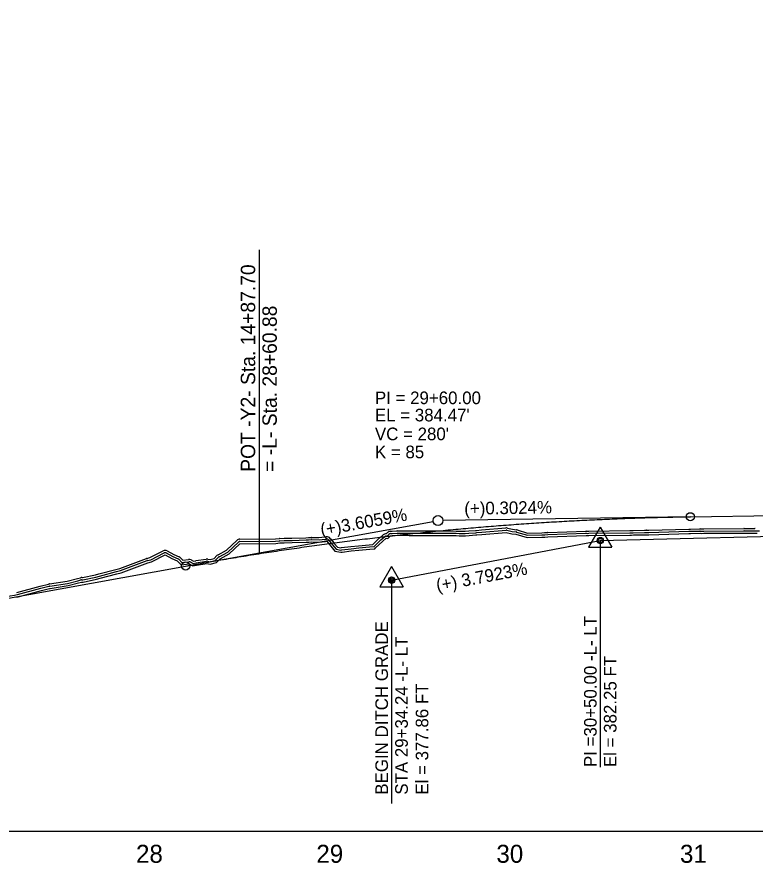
# Model space of a CAD drawing. Extents: x 1625686 to 1640492, y 1161393 to 1175642.
# Drawn here: x 1631930.7 to 1632340.2, y 1174893.1 to 1175362.5 of the extents above; entities that cross this region are included whole.
import ezdxf

# ---------------------------------------------------------------- set-up
doc = ezdxf.new("R2010")
doc.units = 0
for name, color, linetype in [('Exist Profile Cell', 7, 'Continuous'), ('Exist Vertical Profile Ground Line', 7, 'Continuous'), ('Exist Vertical Profile Horizontal Axis Label Major', 7, 'Continuous'), ('Prop PFL Text', 7, 'Continuous'), ('Prop Vertical Profile Curve Label', 7, 'Continuous'), ('Prop Vertical Profile Ditch Grade Left', 7, 'Continuous'), ('Prop Vertical Profile Ditch Grade Left Label', 7, 'Continuous'), ('Prop Vertical Profile Grade', 7, 'Continuous'), ('Prop Vertical Profile Grade Label', 7, 'Continuous'), ('Prop VPI Ditch Grade Left Label', 7, 'Continuous'), ('Prop VPI Label', 7, 'Continuous'), ('Scratch_Level_1', 7, 'Continuous'), ('Scratch_Level_3', 7, 'Continuous'), ('Scratch_Level_5', 7, 'Continuous')]:
    doc.layers.add(name, color=color, linetype=linetype)

msp = doc.modelspace()

# ---------------------------------------------------------------- linework, layer by layer
at = {"layer": 'Exist Profile Cell'}
msp.add_line((1630204.31, 1174910.79), (1634670.63, 1174910.79), dxfattribs=at)
at = {"layer": 'Exist Vertical Profile Ground Line'}
msp.add_lwpolyline([(1631930.43, 1175040.63), (1631931.35, 1175040.89), (1631944.27, 1175044.34), (1631948.74, 1175045.44), (1631949.08, 1175045.51), (1631959.09, 1175047.07), (1631964.89, 1175048.52), (1631966.54, 1175048.97), (1631966.94, 1175048.95), (1631967.49, 1175048.99), (1631974.82, 1175050.58), (1631976.86, 1175051.11), (1631986.19, 1175053.62), (1631988.61, 1175054.19), (1632003.39, 1175059.72), (1632005.36, 1175060.23), (1632012.88, 1175064.05), (1632016.68, 1175062.06), (1632019.64, 1175060.73), (1632021.81, 1175058.61), (1632026.2, 1175059.03), (1632028.28, 1175058), (1632030.37, 1175058.42), (1632036.09, 1175059.3), (1632037.88, 1175058.92), (1632041.38, 1175059.8), (1632043.45, 1175061.95), (1632048.5, 1175064.66), (1632054.43, 1175070.26), (1632074.26, 1175070.42), (1632076.53, 1175070.68), (1632078.98, 1175070.77), (1632083.33, 1175070.9), (1632091.13, 1175071.13), (1632092.6, 1175071.22), (1632094.03, 1175071.31), (1632098.34, 1175071.15), (1632101.87, 1175071.54), (1632102.62, 1175071.63), (1632104.82, 1175068.92), (1632107.09, 1175066.11), (1632110.32, 1175065.52), (1632111.14, 1175065.61), (1632116.2, 1175066.27), (1632120.41, 1175066.66), (1632126.39, 1175067.21), (1632129.18, 1175067.43), (1632129.68, 1175067.92), (1632133.45, 1175071.52), (1632135.56, 1175073.3), (1632136.46, 1175073.17), (1632137.99, 1175074.71), (1632138.95, 1175074.78), (1632141.71, 1175074.97), (1632148.22, 1175074.93), (1632157.49, 1175074.89), (1632163.42, 1175074.86), (1632165.48, 1175074.89), (1632166.76, 1175074.88), (1632174.29, 1175074.81), (1632176.03, 1175074.72), (1632179.5, 1175074.72), (1632181.5, 1175074.86), (1632185.3, 1175075.15), (1632185.89, 1175075.2), (1632188.7, 1175075.48), (1632202.18, 1175076.53), (1632205.23, 1175075.78), (1632207.53, 1175075.56), (1632213.68, 1175073.7), (1632221.97, 1175073.89), (1632223.56, 1175073.94), (1632225.25, 1175074.09), (1632246.41, 1175074.8), (1632247.17, 1175074.78), (1632247.99, 1175074.79), (1632270.71, 1175075.11), (1632271.65, 1175075.1), (1632272.66, 1175075.13), (1632278.92, 1175075.22), (1632280.02, 1175075.26), (1632281.22, 1175075.24), (1632303.44, 1175075.91), (1632304.45, 1175075.92), (1632309.66, 1175076.08), (1632310.69, 1175076.02), (1632311.81, 1175076.08), (1632334.03, 1175076.19), (1632335.18, 1175076.16), (1632340.04, 1175076.18), (1632341.29, 1175076.11)], dxfattribs=at)
at = {"layer": 'Prop PFL Text'}
msp.add_line((1632065.19, 1175064.77), (1632065.19, 1175233.25), dxfattribs=at)
at = {"layer": 'Prop Vertical Profile Curve Label'}
for centre in [(1632304.31, 1175085.25), (1632024.31, 1175057.9)]:
    msp.add_circle(centre, 2.25, dxfattribs=at)
at = {"layer": 'Prop Vertical Profile Ditch Grade Left'}
msp.add_lwpolyline([(1632138.55, 1175050.09), (1632254.31, 1175072.04), (1632654.31, 1175082.04)], dxfattribs=at)
at = {"layer": 'Prop Vertical Profile Grade'}
for p, q in [((1632304.31, 1175085.25), (1632929.31, 1175094.7)), ((1631884.31, 1175032.65), (1632024.31, 1175057.9))]:
    msp.add_line(p, q, dxfattribs=at)
msp.add_spline([(1632024.31, 1175057.9), (1632029.91, 1175058.9), (1632035.51, 1175059.88), (1632041.11, 1175060.84), (1632046.71, 1175061.79), (1632052.31, 1175062.71), (1632057.91, 1175063.62), (1632063.51, 1175064.51), (1632069.11, 1175065.38), (1632074.71, 1175066.23), (1632080.31, 1175067.07), (1632085.91, 1175067.88), (1632091.51, 1175068.68), (1632097.11, 1175069.46), (1632102.71, 1175070.22), (1632108.31, 1175070.96), (1632113.91, 1175071.68), (1632119.51, 1175072.39), (1632125.11, 1175073.07), (1632130.71, 1175073.74), (1632136.31, 1175074.39), (1632141.91, 1175075.02), (1632147.51, 1175075.63), (1632153.11, 1175076.22), (1632158.71, 1175076.8), (1632164.31, 1175077.36), (1632169.91, 1175077.89), (1632175.51, 1175078.41), (1632181.11, 1175078.91), (1632186.71, 1175079.4), (1632192.31, 1175079.86), (1632197.91, 1175080.31), (1632203.51, 1175080.73), (1632209.11, 1175081.14), (1632214.71, 1175081.53), (1632220.31, 1175081.9), (1632225.91, 1175082.26), (1632231.51, 1175082.59), (1632237.11, 1175082.91), (1632242.71, 1175083.2), (1632248.31, 1175083.48), (1632253.91, 1175083.74), (1632259.51, 1175083.98), (1632265.11, 1175084.21), (1632270.71, 1175084.41), (1632276.31, 1175084.6), (1632281.91, 1175084.77), (1632287.51, 1175084.92), (1632293.11, 1175085.05), (1632298.71, 1175085.16), (1632304.31, 1175085.25)], degree=3, dxfattribs=at)
at = {"layer": 'Prop VPI Ditch Grade Left Label'}
for p, q in [((1632254.31, 1175079.52), (1632247.86, 1175068.32)), ((1632254.31, 1175079.52), (1632260.81, 1175068.32)), ((1632254.31, 1175072.04), (1632254.31, 1174946.4)), ((1632247.86, 1175068.32), (1632260.81, 1175068.32)), ((1632138.55, 1175057.57), (1632132.1, 1175046.37)), ((1632138.55, 1175057.57), (1632145.05, 1175046.37)), ((1632132.1, 1175046.37), (1632145.05, 1175046.37)), ((1632138.55, 1175050.09), (1632138.55, 1174926.27))]:
    msp.add_line(p, q, dxfattribs=at)
for centre, radius in [((1632254.31, 1175072.04), 1.75), ((1632254.31, 1175072.04), 1.2), ((1632138.55, 1175050.09), 1.75), ((1632138.55, 1175050.09), 1.2), ((1632138.55, 1175050.09), 0.5)]:
    msp.add_circle(centre, radius, dxfattribs=at)
at = {"layer": 'Prop VPI Label'}
for p, q in [((1632304.31, 1175085.25), (1632167.06, 1175083.18)), ((1632024.31, 1175057.9), (1632161.61, 1175082.65))]:
    msp.add_line(p, q, dxfattribs=at)
msp.add_circle((1632164.31, 1175083.14), 2.75, dxfattribs=at)
at = {"layer": 'Scratch_Level_1'}
for p, q in [((1632188.5, 1175077.97), (1632201.98, 1175079.02)), ((1632311.8, 1175078.58), (1632334.01, 1175078.69)), ((1632131.84, 1175073.42), (1632133.95, 1175075.21)), ((1632132.64, 1175072.47), (1632134.75, 1175074.25)), ((1632135.55, 1175075.8), (1632136.22, 1175076.47)), ((1632188.6, 1175076.72), (1632202.08, 1175077.77)), ((1632225.16, 1175076.59), (1632246.33, 1175077.3)), ((1632225.2, 1175075.34), (1632246.37, 1175076.05)), ((1632311.81, 1175077.33), (1632334.02, 1175077.44)), ((1632076.44, 1175073.18), (1632078.89, 1175073.27)), ((1632076.49, 1175071.93), (1632078.93, 1175072.02)), ((1632103.58, 1175072.42), (1632105.79, 1175069.71)), ((1632104.55, 1175073.2), (1632106.76, 1175070.5)), ((1632029.99, 1175060.89), (1632035.71, 1175061.77)), ((1632030.18, 1175059.65), (1632035.9, 1175060.53)), ((1631930.7, 1175043.3), (1631943.62, 1175046.76)), ((1631943.67, 1175046.77), (1631948.15, 1175047.87)), ((1631943.97, 1175045.56), (1631948.45, 1175046.66)), ((1631948.25, 1175047.89), (1631948.58, 1175047.96)), ((1631948.5, 1175046.67), (1631948.83, 1175046.74)), ((1631931.02, 1175042.09), (1631943.94, 1175045.55))]:
    msp.add_line(p, q, dxfattribs=at)
for points in [[(1632202.77, 1175078.96), (1632205.64, 1175078.26), (1632207.77, 1175078.05)], [(1632334.09, 1175078.69), (1632335.2, 1175078.66), (1632340.03, 1175078.68)], [(1632094.12, 1175073.81), (1632098.25, 1175073.65), (1632101.59, 1175074.03), (1632102.34, 1175074.11)], [(1632135.74, 1175074.54), (1632136.02, 1175074.5), (1632137.11, 1175075.59)], [(1632137.82, 1175077.21), (1632138.78, 1175077.27), (1632141.54, 1175077.46)], [(1632137.91, 1175075.96), (1632138.87, 1175076.03), (1632141.62, 1175076.21)], [(1632141.71, 1175076.22), (1632148.23, 1175076.18), (1632157.5, 1175076.14), (1632163.42, 1175076.11), (1632165.46, 1175076.14)], [(1632141.72, 1175077.47), (1632148.23, 1175077.43), (1632157.5, 1175077.39), (1632163.41, 1175077.36), (1632165.44, 1175077.39)], [(1632165.49, 1175076.14), (1632166.77, 1175076.13), (1632174.3, 1175076.06)], [(1632165.5, 1175077.39), (1632166.79, 1175077.38), (1632174.31, 1175077.31)], [(1632174.35, 1175076.06), (1632176.06, 1175075.97), (1632179.45, 1175075.97), (1632181.4, 1175076.11), (1632185.21, 1175076.4), (1632185.78, 1175076.44), (1632188.57, 1175076.72)], [(1632174.41, 1175077.31), (1632176.1, 1175077.22), (1632179.41, 1175077.22), (1632181.31, 1175077.36), (1632185.11, 1175077.65), (1632185.67, 1175077.69), (1632188.45, 1175077.97)], [(1632202.47, 1175077.74), (1632205.43, 1175077.02), (1632207.65, 1175076.81)], [(1632207.89, 1175076.76), (1632213.85, 1175074.96), (1632221.94, 1175075.14), (1632223.48, 1175075.18), (1632225.13, 1175075.34)], [(1632208.25, 1175077.96), (1632214.02, 1175076.21), (1632221.9, 1175076.39), (1632223.41, 1175076.43), (1632225.02, 1175076.58)], [(1632246.44, 1175076.05), (1632247.18, 1175076.03), (1632247.98, 1175076.04), (1632270.69, 1175076.36)], [(1632246.46, 1175077.3), (1632247.2, 1175077.28), (1632247.97, 1175077.29), (1632270.67, 1175077.61)], [(1632270.73, 1175076.36), (1632271.64, 1175076.35), (1632272.61, 1175076.38)], [(1632270.76, 1175077.61), (1632271.63, 1175077.6), (1632272.57, 1175077.63)], [(1632272.62, 1175077.63), (1632278.86, 1175077.72), (1632279.94, 1175077.76)], [(1632272.64, 1175076.38), (1632278.89, 1175076.47), (1632279.98, 1175076.51)], [(1632280.05, 1175076.51), (1632281.21, 1175076.49), (1632303.41, 1175077.16)], [(1632280.07, 1175077.76), (1632281.21, 1175077.74), (1632303.37, 1175078.41)], [(1632303.43, 1175078.41), (1632304.4, 1175078.42), (1632309.58, 1175078.57)], [(1632303.44, 1175077.16), (1632304.42, 1175077.17), (1632309.62, 1175077.33)], [(1632309.72, 1175077.32), (1632310.69, 1175077.28), (1632311.75, 1175077.33)], [(1632309.79, 1175078.57), (1632310.69, 1175078.53), (1632311.69, 1175078.58)], [(1632334.06, 1175077.44), (1632335.19, 1175077.41), (1632340.03, 1175077.43)], [(1632340.11, 1175077.43), (1632341.34, 1175077.36), (1632342.7, 1175077.34)], [(1632042.27, 1175064.15), (1632047.02, 1175066.71), (1632052.71, 1175072.08)], [(1632042.86, 1175063.05), (1632047.76, 1175065.68), (1632053.57, 1175071.17)], [(1632054.41, 1175072.76), (1632074.1, 1175072.92), (1632076.24, 1175073.17)], [(1632054.42, 1175071.51), (1632074.18, 1175071.67), (1632076.39, 1175071.92)], [(1632078.91, 1175073.27), (1632083.26, 1175073.4), (1632091.01, 1175073.62), (1632092.44, 1175073.71), (1632093.87, 1175073.81)], [(1632078.94, 1175072.02), (1632083.3, 1175072.15), (1632091.07, 1175072.37), (1632092.52, 1175072.47), (1632093.95, 1175072.56)], [(1632094.08, 1175072.56), (1632098.29, 1175072.4), (1632101.73, 1175072.78), (1632102.48, 1175072.87)], [(1632105.79, 1175069.71), (1632107.77, 1175067.26), (1632110.36, 1175066.78), (1632110.99, 1175066.86), (1632116.04, 1175067.51)], [(1632106.76, 1175070.49), (1632108.45, 1175068.4), (1632110.4, 1175068.04), (1632110.83, 1175068.1), (1632115.87, 1175068.75)], [(1632115.97, 1175068.76), (1632120.18, 1175069.15), (1632126.16, 1175069.7)], [(1632126.19, 1175069.7), (1632128.09, 1175069.86), (1632131.72, 1175073.32)], [(1632126.29, 1175068.46), (1632128.64, 1175068.65), (1632128.82, 1175068.82), (1632132.59, 1175072.42)], [(1632002.76, 1175062.14), (1632004.47, 1175062.59), (1632011.75, 1175066.28)], [(1632003.08, 1175060.93), (1632004.91, 1175061.41), (1632012.31, 1175065.16)], [(1632013.46, 1175065.15), (1632017.22, 1175063.18), (1632020.16, 1175061.87)], [(1632014.04, 1175066.26), (1632017.77, 1175064.31), (1632020.67, 1175063.01)], [(1632116.08, 1175067.52), (1632120.3, 1175067.91), (1632126.27, 1175068.46)], [(1631985.61, 1175056.05), (1631987.88, 1175056.59), (1632002.52, 1175062.06)], [(1631985.9, 1175054.83), (1631988.25, 1175055.39), (1632002.95, 1175060.89)], [(1632020.52, 1175061.62), (1632022.27, 1175059.91), (1632026.08, 1175060.27)], [(1632021.39, 1175062.51), (1632022.73, 1175061.21), (1632025.96, 1175061.52)], [(1632026.76, 1175060.15), (1632028.45, 1175059.31), (1632030.13, 1175059.64)], [(1632027.31, 1175061.27), (1632028.63, 1175060.62), (1632029.88, 1175060.87)], [(1632036.35, 1175060.52), (1632037.86, 1175060.2), (1632040.73, 1175060.92), (1632042.55, 1175062.82)], [(1632036.61, 1175061.74), (1632037.83, 1175061.48), (1632040.07, 1175062.05), (1632041.65, 1175063.68)], [(1631966.65, 1175051.47), (1631966.91, 1175051.46), (1631967.14, 1175051.47), (1631974.24, 1175053.01), (1631976.22, 1175053.53), (1631985.54, 1175056.03)], [(1631948.69, 1175047.98), (1631958.59, 1175049.52), (1631964.26, 1175050.94), (1631965.89, 1175051.38)], [(1631966.59, 1175050.22), (1631966.93, 1175050.2), (1631967.32, 1175050.23), (1631974.53, 1175051.8), (1631976.54, 1175052.32), (1631985.87, 1175054.82)], [(1631948.88, 1175046.75), (1631958.84, 1175048.29), (1631964.57, 1175049.73), (1631966.21, 1175050.18)], [(1631907.62, 1175038.35), (1631929.34, 1175041.69), (1631930.14, 1175041.85), (1631931.01, 1175042.09)]]:
    msp.add_lwpolyline(points, dxfattribs=at)
for centre, radius, start, end in [((1632202.18, 1175076.53), 2.5, 76.3014, 94.4507), ((1632334.03, 1175076.19), 2.5, 88.62, 90.2786), ((1632340.04, 1175076.18), 2.5, 86.5505, 90.2705), ((1632102.62, 1175071.63), 2.5, 39.1789, 96.4197), ((1632135.56, 1175073.3), 2.5, 90.2425, 130.2104), ((1632135.56, 1175073.3), 1.25, 81.8224, 130.2104), ((1632137.99, 1175074.71), 2.5, 93.904, 135.2284), ((1632137.99, 1175074.71), 1.25, 93.904, 135.2284), ((1632141.71, 1175074.97), 2.5, 89.7082, 93.9099), ((1632141.71, 1175074.97), 1.25, 89.7082, 93.9099), ((1632165.48, 1175074.89), 2.5, 89.4274, 90.9715), ((1632165.48, 1175074.89), 1.25, 89.4274, 90.9715), ((1632174.29, 1175074.81), 1.25, 87.2287, 89.4429), ((1632174.29, 1175074.81), 2.5, 87.2287, 89.4429), ((1632188.7, 1175075.48), 2.5, 94.4507, 95.6759), ((1632188.7, 1175075.48), 1.25, 94.4507, 95.6759), ((1632202.18, 1175076.53), 1.25, 76.3014, 94.4507), ((1632207.53, 1175075.56), 1.25, 73.1705, 84.5284), ((1632207.53, 1175075.56), 2.5, 73.1705, 84.5284), ((1632225.25, 1175074.09), 2.5, 91.9196, 95.2559), ((1632225.25, 1175074.09), 1.25, 91.9196, 95.2559), ((1632246.41, 1175074.8), 2.5, 88.7473, 91.9196), ((1632246.41, 1175074.8), 1.25, 88.7473, 91.9196), ((1632270.71, 1175075.11), 2.5, 88.8166, 90.8293), ((1632270.71, 1175075.11), 1.25, 88.8166, 90.8293), ((1632272.66, 1175075.13), 2.5, 90.8307, 92.1022), ((1632272.66, 1175075.13), 1.25, 90.8307, 92.1022), ((1632280.02, 1175075.26), 2.5, 88.9436, 91.818), ((1632280.02, 1175075.26), 1.25, 88.9436, 91.818), ((1632303.44, 1175075.91), 2.5, 90.2145, 91.7412), ((1632303.44, 1175075.91), 1.25, 90.2145, 91.7412), ((1632309.66, 1175076.08), 2.5, 87.0819, 91.7596), ((1632309.66, 1175076.08), 1.25, 87.0819, 91.7596), ((1632311.81, 1175076.08), 2.5, 90.2786, 92.768), ((1632311.81, 1175076.08), 1.25, 90.2786, 92.768), ((1632334.03, 1175076.19), 1.25, 88.62, 90.2786), ((1632340.04, 1175076.18), 1.25, 86.5505, 90.2705), ((1632054.43, 1175070.26), 2.5, 90.4564, 133.3657), ((1632054.43, 1175070.26), 1.25, 90.4564, 133.3657), ((1632076.53, 1175070.68), 2.5, 92.0965, 96.6707), ((1632076.53, 1175070.68), 1.25, 92.0965, 96.6707), ((1632078.98, 1175070.77), 2.5, 91.6606, 92.0965), ((1632078.98, 1175070.77), 1.25, 91.6606, 92.0965), ((1632094.03, 1175071.31), 2.5, 87.7962, 93.6693), ((1632094.03, 1175071.31), 1.25, 87.7962, 93.6693), ((1632102.62, 1175071.63), 1.25, 39.1789, 96.4197), ((1632104.82, 1175068.92), 1.25, 38.9141, 39.1789), ((1632104.82, 1175068.92), 2.5, 38.9141, 39.1789), ((1632126.39, 1175067.21), 2.5, 94.6011, 95.2504), ((1632133.45, 1175071.52), 2.5, 130.2104, 133.6968), ((1632133.45, 1175071.52), 1.25, 130.2104, 133.6968), ((1632012.88, 1175064.05), 2.5, 62.3402, 116.8749), ((1632012.88, 1175064.05), 1.25, 62.3402, 116.8749), ((1632116.2, 1175066.27), 2.5, 95.2395, 97.4391), ((1632116.2, 1175066.27), 1.25, 95.2395, 97.4391), ((1632126.39, 1175067.21), 1.25, 94.6011, 95.2504), ((1632003.39, 1175059.72), 2.5, 104.6116, 110.5151), ((1632003.39, 1175059.72), 1.25, 104.6116, 110.5151), ((1632019.64, 1175060.73), 1.25, 45.6673, 65.8397), ((1632019.64, 1175060.73), 2.5, 45.6673, 65.8397), ((1632026.2, 1175059.03), 2.5, 63.6978, 95.5265), ((1632026.2, 1175059.03), 1.25, 63.6978, 95.5265), ((1632030.37, 1175058.42), 2.5, 98.7325, 101.2323), ((1632036.09, 1175059.3), 2.5, 78.0081, 98.7325), ((1632036.09, 1175059.3), 1.25, 78.0081, 98.7325), ((1632043.45, 1175061.95), 2.5, 118.2328, 136.1032), ((1632043.45, 1175061.95), 1.25, 118.2328, 136.1032), ((1631986.19, 1175053.62), 2.5, 103.3927, 105.0267), ((1632030.37, 1175058.42), 1.25, 98.7325, 101.2323), ((1631966.54, 1175048.97), 2.5, 87.4827, 105.1196), ((1631986.19, 1175053.62), 1.25, 103.3927, 105.0267), ((1631944.27, 1175044.34), 2.5, 103.8307, 104.9724), ((1631948.74, 1175045.44), 2.5, 101.4559, 103.8307), ((1631948.74, 1175045.44), 1.25, 101.4559, 103.8307), ((1631949.08, 1175045.51), 2.5, 98.8376, 101.4559), ((1631949.08, 1175045.51), 1.25, 98.8376, 101.4559), ((1631966.54, 1175048.97), 1.25, 87.4827, 105.1196), ((1631931.35, 1175040.89), 1.25, 104.9724, 105.664), ((1631944.27, 1175044.34), 1.25, 103.8307, 104.9724)]:
    msp.add_arc(centre, radius, start, end, dxfattribs=at)
at = {"layer": 'Scratch_Level_3'}
msp.add_lwpolyline([(1630204.31, 1174910.79), (1634341.72, 1174910.79), (1634341.72, 1175362.47)], dxfattribs=at)
at = {"layer": 'Scratch_Level_5'}
msp.add_lwpolyline([(1631930.43, 1175040.63), (1631931.35, 1175040.89), (1631944.27, 1175044.34), (1631948.74, 1175045.44), (1631949.08, 1175045.51), (1631959.09, 1175047.07), (1631964.89, 1175048.52), (1631966.54, 1175048.97), (1631966.94, 1175048.95), (1631967.49, 1175048.99), (1631974.82, 1175050.58), (1631976.86, 1175051.11), (1631986.19, 1175053.62), (1631988.61, 1175054.19), (1632003.39, 1175059.72), (1632005.36, 1175060.23), (1632012.88, 1175064.05), (1632016.68, 1175062.06), (1632019.64, 1175060.73), (1632021.81, 1175058.61), (1632026.2, 1175059.03), (1632028.28, 1175058), (1632030.37, 1175058.42), (1632036.09, 1175059.3), (1632037.88, 1175058.92), (1632041.38, 1175059.8), (1632043.45, 1175061.95), (1632048.5, 1175064.66), (1632054.43, 1175070.26), (1632074.26, 1175070.42), (1632076.53, 1175070.68), (1632078.98, 1175070.77), (1632083.33, 1175070.9), (1632091.13, 1175071.13), (1632092.6, 1175071.22), (1632094.03, 1175071.31), (1632098.34, 1175071.15), (1632101.87, 1175071.54), (1632102.62, 1175071.63), (1632104.82, 1175068.92), (1632107.09, 1175066.11), (1632110.32, 1175065.52), (1632111.14, 1175065.61), (1632116.2, 1175066.27), (1632120.41, 1175066.66), (1632126.39, 1175067.21), (1632129.18, 1175067.43), (1632129.68, 1175067.92), (1632133.45, 1175071.52), (1632135.56, 1175073.3), (1632136.46, 1175073.17), (1632137.99, 1175074.71), (1632138.95, 1175074.78), (1632141.71, 1175074.97), (1632148.22, 1175074.93), (1632157.49, 1175074.89), (1632163.42, 1175074.86), (1632165.48, 1175074.89), (1632166.76, 1175074.88), (1632174.29, 1175074.81), (1632176.03, 1175074.72), (1632179.5, 1175074.72), (1632181.5, 1175074.86), (1632185.3, 1175075.15), (1632185.89, 1175075.2), (1632188.7, 1175075.48), (1632202.18, 1175076.53), (1632205.23, 1175075.78), (1632207.53, 1175075.56), (1632213.68, 1175073.7), (1632221.97, 1175073.89), (1632223.56, 1175073.94), (1632225.25, 1175074.09), (1632246.41, 1175074.8), (1632247.17, 1175074.78), (1632247.99, 1175074.79), (1632270.71, 1175075.11), (1632271.65, 1175075.1), (1632272.66, 1175075.13), (1632278.92, 1175075.22), (1632280.02, 1175075.26), (1632281.22, 1175075.24), (1632303.44, 1175075.91), (1632304.45, 1175075.92), (1632309.66, 1175076.08), (1632310.69, 1175076.02), (1632311.81, 1175076.08), (1632334.03, 1175076.19), (1632335.18, 1175076.16), (1632340.04, 1175076.18), (1632341.29, 1175076.11)], dxfattribs=at)

# ---------------------------------------------------------------- texts
at = {"layer": 'Exist Vertical Profile Horizontal Axis Label Major'}
for s, p in [('28', (1631996.78, 1174893.29)), ('29', (1632096.82, 1174893.29)), ('30', (1632196.7, 1174893.29)), ('31', (1632298.54, 1174893.29))]:
    msp.add_text(s, height=10, dxfattribs=at).set_placement(p)
at = {"layer": 'Prop PFL Text'}
for s, p in [('POT -Y2- Sta. 14+87.70', (1632062.88, 1175110.16)), ('= -L- Sta. 28+60.88', (1632074.88, 1175110.16))]:
    msp.add_text(s, height=8, rotation=90, dxfattribs=at).set_placement(p)
at = {"layer": 'Prop Vertical Profile Curve Label'}
for s, p in [("VC = 280'", (1632129.31, 1175127.69)), ('K = 85', (1632129.31, 1175117.69))]:
    msp.add_text(s, height=7, dxfattribs=at).set_placement(p)
at = {"layer": 'Prop Vertical Profile Ditch Grade Left Label'}
msp.add_text('(+) 3.7923%', height=7, rotation=10.7368, dxfattribs=at).set_placement((1632163.96, 1175043.7))
at = {"layer": 'Prop Vertical Profile Grade Label'}
for s, rotation, p in [('(+)0.3024%', 0.8663, (1632178.92, 1175086.36)), ('(+)3.6059%', 10.2203, (1632099.69, 1175074.53))]:
    msp.add_text(s, height=7, rotation=rotation, dxfattribs=at).set_placement(p)
at = {"layer": 'Prop VPI Ditch Grade Left Label'}
for s, p in [('PI =30+50.00 -L- LT', (1632252.31, 1174946.4)), ('BEGIN DITCH GRADE', (1632136.55, 1174931.09)), ('STA 29+34.24 -L- LT', (1632147.55, 1174931.09)), ('El = 382.25 FT', (1632263.31, 1174946.4)), ('El = 377.86 FT', (1632158.93, 1174931.09))]:
    msp.add_text(s, height=7, rotation=90, dxfattribs=at).set_placement(p)
at = {"layer": 'Prop VPI Label'}
for s, p in [('PI = 29+60.00', (1632129.31, 1175147.69)), ("EL = 384.47'", (1632129.31, 1175138.14))]:
    msp.add_text(s, height=7, dxfattribs=at).set_placement(p)

doc.saveas('drawing.dxf')
